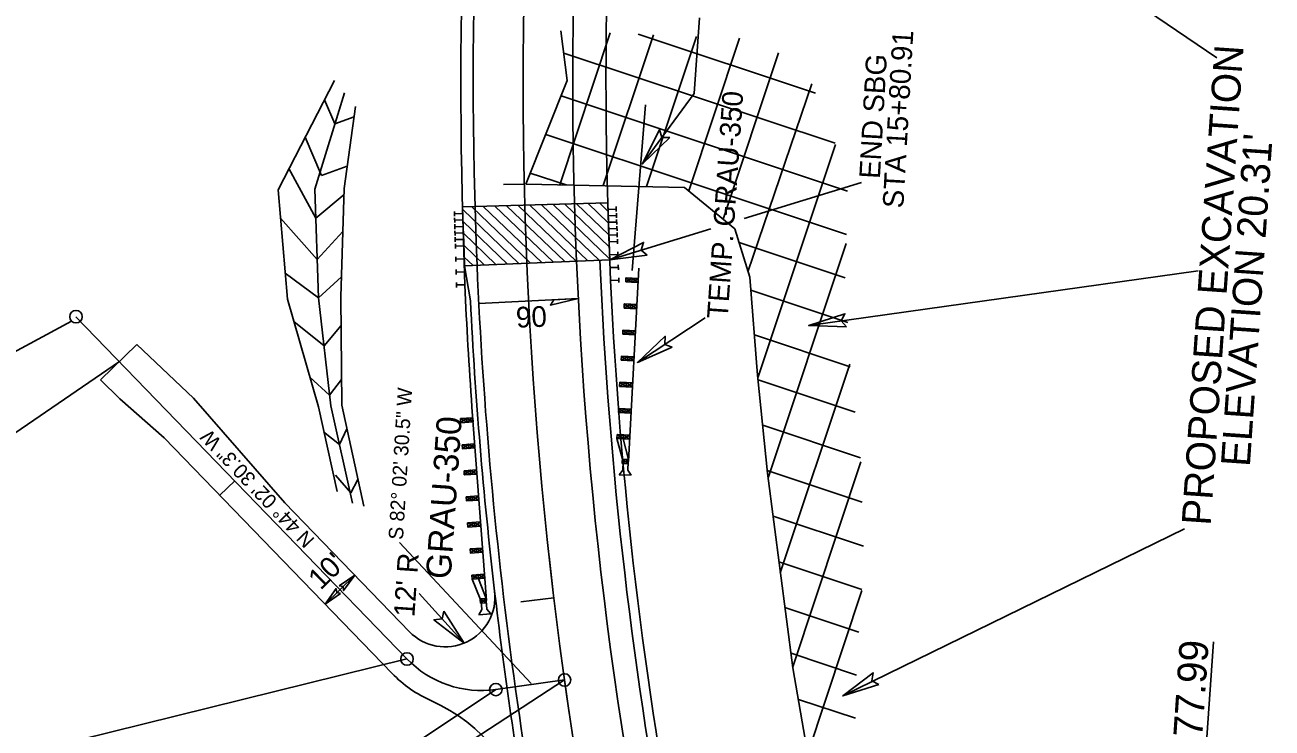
# Model space of a CAD drawing. Extents: x 2599146 to 2600072, y 728518 to 730269.
# Drawn here: x 2599320.7 to 2599621.3, y 729076.9 to 729246.4 of the extents above; entities that cross this region are included whole.
import ezdxf

# ---------------------------------------------------------------- set-up
doc = ezdxf.new("R2010")
doc.units = 0
for name, color, linetype in [('Default', 7, 'Continuous'), ('Old_Level_11', 7, 'Continuous'), ('Prop Conc Shoulder Berm Gutter', 7, 'Continuous'), ('Prop Dimension', 7, 'Continuous'), ('Prop Dimension Text', 7, 'Continuous'), ('Prop Drainage Ditch Base Lines', 7, 'Continuous'), ('Prop EOT', 7, 'Continuous'), ('Prop Guardrail', 7, 'Continuous'), ('Prop Guardrail Anchor Unit CELL', 7, 'Continuous'), ('Prop Horizontal Alignment', 7, 'Continuous'), ('Prop Horizontal Alignment Direction Label', 7, 'Continuous'), ('Prop Horizontal Alignment Station Label', 7, 'Continuous'), ('Prop Horizontal Alignment Tick Large', 7, 'Continuous'), ('Prop Horizontal Alignment Tick Small', 7, 'Continuous'), ('Prop Lane Lines', 7, 'Continuous'), ('Prop Roadway Bridge', 7, 'Continuous'), ('Prop Structure Anchor Unit CELL', 7, 'Continuous'), ('Prop Superelevation Label', 7, 'Continuous'), ('Prop Temporary Shoring', 7, 'Continuous'), ('Prop Temporary Shoring Leader Line', 7, 'Continuous'), ('Prop Temporary Shoring Text', 7, 'Continuous'), ('Prop Terminator CELL', 7, 'Continuous')]:
    doc.layers.add(name, color=color, linetype=linetype)

msp = doc.modelspace()

# ---------------------------------------------------------------- linework, layer by layer
at = {"layer": 'Default'}
for p, q in [((2599449.59, 729207.86), (2599461.77, 729244.49)), ((2599451.39, 729233.01), (2599449.88, 729244.99)), ((2599460.06, 729207.65), (2599472.16, 729244.05)), ((2599511.25, 729229.98), (2599468.49, 729244.2)), ((2599470.52, 729207.43), (2599482.56, 729243.61)), ((2599480.71, 729206.37), (2599492.95, 729243.17)), ((2599515.96, 729217.88), (2599450.55, 729239.63)), ((2599488.98, 729199.56), (2599502.34, 729239.71)), ((2599441.44, 729208.03), (2599451.39, 729233.01)), ((2599494.92, 729186.85), (2599510.38, 729232.21)), ((2599518.98, 729206.33), (2599449.91, 729229.31)), ((2599518.71, 729195.89), (2599446.21, 729220)), ((2599497.34, 729161.3), (2599516.06, 729217.61)), ((2599451.11, 729207.83), (2599442.5, 729210.69)), ((2599479.66, 729207.24), (2599441.44, 729208.03)), ((2599491.82, 729197.23), (2599479.66, 729207.24)), ((2599495.43, 729185.58), (2599491.82, 729197.23)), ((2599518.43, 729185.44), (2599492.83, 729193.95)), ((2599499.86, 729137.2), (2599518.65, 729193.69)), ((2599497.29, 729161.95), (2599495.43, 729185.58)), ((2599519.07, 729174.69), (2599495.68, 729182.47)), ((2599519.58, 729163.98), (2599496.52, 729171.65)), ((2599502.77, 729114.29), (2599519.51, 729164.6)), ((2599499.71, 729138.37), (2599497.29, 729161.95)), ((2599520.84, 729153.02), (2599497.4, 729160.82)), ((2599522.1, 729142.07), (2599498.52, 729149.91)), ((2599522.54, 729131.38), (2599499.63, 729139)), ((2599502.7, 729114.87), (2599499.71, 729138.37)), ((2599505.79, 729091.67), (2599522.21, 729141.04)), ((2599522.85, 729120.74), (2599501.03, 729128)), ((2599522.46, 729110.33), (2599502.43, 729116.99)), ((2599505.83, 729091.4), (2599502.7, 729114.87)), ((2599509.38, 729070.78), (2599522.44, 729110.03)), ((2599521.73, 729100.03), (2599503.88, 729105.97)), ((2599521.16, 729089.68), (2599505.36, 729094.94)), ((2599509.85, 729068.07), (2599505.83, 729091.4)), ((2599520.87, 729079.24), (2599507.14, 729083.81))]:
    msp.add_line(p, q, dxfattribs=at)
at = {"layer": 'Old_Level_11'}
msp.add_line((2599484.66, 729175.76), (2599468.34, 729165.03), dxfattribs=at)
at = {"layer": 'Prop Conc Shoulder Berm Gutter'}
msp.add_arc((2600480.74, 729232.47), 1022.34, 182.39886, 190.87052, dxfattribs=at)
at = {"layer": 'Prop Dimension'}
for p, q in [((2599509.48, 729305.39), (2599608.02, 729238.47)), ((2599494.07, 729199.72), (2599522.35, 729208.38)), ((2599461.64, 729189.78), (2599485.99, 729197.24)), ((2599509.63, 729173.91), (2599603.55, 729187.15)), ((2599517.84, 729084.66), (2599600.18, 729124.92)), ((2599400.18, 729113.75), (2599393, 729106.79))]:
    msp.add_line(p, q, dxfattribs=at)
at = {"layer": 'Prop Dimension Text'}
msp.add_line((2599415.68, 729109.34), (2599426.53, 729097.36), dxfattribs=at)
at = {"layer": 'Prop Drainage Ditch Base Lines'}
for p, q in [((2599381.67, 729206.63), (2599395.27, 729233.01)), ((2599390.55, 729206.83), (2599397.7, 729230.03)), ((2599395.38, 729222.52), (2599392.87, 729228.37)), ((2599397.63, 729207), (2599400.38, 729226.74)), ((2599395.38, 729222.52), (2599400.04, 729224.25)), ((2599392.18, 729210.07), (2599388.21, 729219.31)), ((2599390.79, 729199.83), (2599384.31, 729211.76)), ((2599392.18, 729210.07), (2599398.38, 729212.38)), ((2599383.95, 729180.28), (2599381.67, 729206.63)), ((2599391.46, 729180.64), (2599390.55, 729206.83)), ((2599390.79, 729199.83), (2599397.59, 729205.5)), ((2599396.85, 729180.89), (2599397.63, 729207)), ((2599391.14, 729189.82), (2599382.26, 729199.8)), ((2599391.14, 729189.82), (2599397.32, 729196.63)), ((2599391.46, 729180.64), (2599383.4, 729186.56)), ((2599391.46, 729180.64), (2599396.99, 729185.68)), ((2599394.39, 729154.57), (2599391.46, 729180.64)), ((2599397.05, 729154.76), (2599396.85, 729180.89)), ((2599391.43, 729154.36), (2599383.95, 729180.28)), ((2599392.76, 729169.06), (2599385.5, 729174.88)), ((2599392.76, 729169.06), (2599396.9, 729173.95)), ((2599394.1, 729157.16), (2599389.38, 729161.47)), ((2599394.1, 729157.16), (2599397, 729160.95)), ((2599395.91, 729133.9), (2599391.43, 729154.36)), ((2599399.62, 729131.1), (2599394.39, 729154.57)), ((2599402.34, 729130.42), (2599397.05, 729154.76)), ((2599396.46, 729145.29), (2599392.61, 729148.28)), ((2599396.46, 729145.29), (2599398.3, 729148.99)), ((2599399.26, 729133.57), (2599395.51, 729137.89)), ((2599399.26, 729133.57), (2599400.94, 729136.85))]:
    msp.add_line(p, q, dxfattribs=at)
at = {"layer": 'Prop EOT'}
for p, q in [((2599428.06, 729179.91), (2599426.67, 729188.31)), ((2599347.67, 729169.36), (2599338.88, 729160.85)), ((2599361.32, 729156.43), (2599347.67, 729169.36)), ((2599343.52, 729156.26), (2599338.88, 729160.85)), ((2599383.31, 729131.2), (2599361.32, 729156.43)), ((2599354.24, 729146.87), (2599343.52, 729156.26)), ((2599409.17, 729090.07), (2599354.24, 729146.87)), ((2599413.36, 729100.13), (2599383.31, 729131.2))]:
    msp.add_line(p, q, dxfattribs=at)
for centre, radius, start, end in [((2600480.74, 729232.47), 1052, 182.39886, 193.57808), ((2600480.74, 729232.47), 1028, 182.39886, 193.57808), ((2600480.74, 729232.47), 1054, 182.85838, 186.68017), ((2599421.98, 729108.47), 12, 224.0417, 6.6802), ((2600480.74, 729232.47), 1054, 186.68017, 189.77021), ((2599430.73, 729110.93), 30, 224.0417, 246.3139), ((2599402.61, 729046.82), 40, 9.7702, 66.3139)]:
    msp.add_arc(centre, radius, start, end, dxfattribs=at)
at = {"layer": 'Prop Guardrail'}
for centre, radius, start, end in [((2600477.16, 729229.69), 1051.44, 182.5033, 184.11474), ((2600478.29, 729232.3), 1017.56, 182.67771, 190.88783)]:
    msp.add_arc(centre, radius, start, end, dxfattribs=at)
at = {"layer": 'Prop Guardrail Anchor Unit CELL'}
for p, q in [((2599468.68, 729187.8), (2599466.16, 729141.12)), ((2599465.55, 729185.43), (2599465.49, 729184.43)), ((2599465.49, 729184.43), (2599467.04, 729185.35)), ((2599468.49, 729184.27), (2599465.49, 729184.43)), ((2599468.54, 729185.27), (2599465.55, 729185.43)), ((2599466.99, 729184.35), (2599465.55, 729185.43)), ((2599467.04, 729185.35), (2599466.99, 729184.35)), ((2599466.99, 729184.35), (2599468.54, 729185.27)), ((2599468.49, 729184.27), (2599466.99, 729184.35)), ((2599467.04, 729185.35), (2599468.49, 729184.27)), ((2599468.54, 729185.27), (2599468.49, 729184.27)), ((2599465.16, 729179.14), (2599465.1, 729178.14)), ((2599465.1, 729178.14), (2599466.68, 729179.06)), ((2599468.15, 729177.98), (2599465.1, 729178.14)), ((2599468.2, 729178.97), (2599465.16, 729179.14)), ((2599466.63, 729178.06), (2599465.16, 729179.14)), ((2599466.68, 729179.06), (2599466.63, 729178.06)), ((2599468.2, 729178.97), (2599466.63, 729178.06)), ((2599466.68, 729179.06), (2599468.15, 729177.98)), ((2599464.82, 729172.85), (2599464.77, 729171.85)), ((2599464.77, 729171.85), (2599466.34, 729172.76)), ((2599467.81, 729171.68), (2599464.77, 729171.85)), ((2599467.86, 729172.68), (2599464.82, 729172.85)), ((2599466.29, 729171.76), (2599464.82, 729172.85)), ((2599466.34, 729172.76), (2599466.29, 729171.76)), ((2599467.86, 729172.68), (2599466.29, 729171.76)), ((2599466.34, 729172.76), (2599467.81, 729171.68)), ((2599464.49, 729166.55), (2599464.44, 729165.55)), ((2599464.44, 729165.55), (2599466.01, 729166.47)), ((2599467.47, 729165.39), (2599464.44, 729165.55)), ((2599467.53, 729166.39), (2599464.49, 729166.55)), ((2599465.96, 729165.47), (2599464.49, 729166.55)), ((2599466.01, 729166.47), (2599465.96, 729165.47)), ((2599467.53, 729166.39), (2599465.96, 729165.47)), ((2599466.01, 729166.47), (2599467.47, 729165.39)), ((2599467.53, 729166.39), (2599467.47, 729165.39)), ((2599464.05, 729160.27), (2599464, 729159.27)), ((2599464, 729159.27), (2599465.62, 729160.18)), ((2599467.19, 729160.1), (2599464.05, 729160.27)), ((2599465.57, 729159.18), (2599464.05, 729160.27)), ((2599465.62, 729160.18), (2599465.57, 729159.18)), ((2599467.19, 729160.1), (2599465.57, 729159.18)), ((2599465.62, 729160.18), (2599467.13, 729159.1)), ((2599467.13, 729159.1), (2599464, 729159.27)), ((2599428.43, 729154.24), (2599431.91, 729107.62)), ((2599463.85, 729153.97), (2599463.8, 729152.97)), ((2599463.8, 729152.97), (2599465.35, 729153.89)), ((2599466.85, 729153.81), (2599463.85, 729153.97)), ((2599465.29, 729152.89), (2599463.85, 729153.97)), ((2599465.35, 729153.89), (2599465.29, 729152.89)), ((2599466.85, 729153.81), (2599465.29, 729152.89)), ((2599465.35, 729153.89), (2599466.79, 729152.81)), ((2599428.62, 729151.71), (2599425.63, 729151.49)), ((2599427.2, 729150.6), (2599425.63, 729151.49)), ((2599425.63, 729151.49), (2599425.7, 729150.49)), ((2599425.7, 729150.49), (2599427.13, 729151.6)), ((2599428.7, 729150.71), (2599425.7, 729150.49)), ((2599427.13, 729151.6), (2599427.2, 729150.6)), ((2599427.13, 729151.6), (2599428.7, 729150.71)), ((2599427.2, 729150.6), (2599428.62, 729151.71)), ((2599428.7, 729150.71), (2599427.2, 729150.6)), ((2599428.62, 729151.71), (2599428.7, 729150.71)), ((2599466.79, 729152.81), (2599463.8, 729152.97)), ((2599463.45, 729147.68), (2599463.39, 729146.68)), ((2599463.39, 729146.68), (2599464.98, 729147.6)), ((2599466.51, 729147.51), (2599463.45, 729147.68)), ((2599464.92, 729146.6), (2599463.45, 729147.68)), ((2599464.98, 729147.6), (2599464.92, 729146.6)), ((2599466.51, 729147.51), (2599464.92, 729146.6)), ((2599464.98, 729147.6), (2599466.45, 729146.51)), ((2599429.09, 729145.43), (2599426.05, 729145.2)), ((2599427.64, 729144.31), (2599426.05, 729145.2)), ((2599426.05, 729145.2), (2599426.12, 729144.2)), ((2599426.12, 729144.2), (2599427.57, 729145.31)), ((2599429.17, 729144.43), (2599426.12, 729144.2)), ((2599427.57, 729145.31), (2599427.64, 729144.31)), ((2599427.57, 729145.31), (2599429.17, 729144.43)), ((2599429.09, 729145.43), (2599427.64, 729144.31)), ((2599466.45, 729146.51), (2599463.39, 729146.68)), ((2599463.39, 729146.68), (2599464.69, 729141.7)), ((2599464.92, 729146.6), (2599466.19, 729141.62)), ((2599464.69, 729141.7), (2599464.64, 729140.7)), ((2599464.64, 729140.7), (2599466.19, 729141.62)), ((2599464.69, 729141.7), (2599464.66, 729141.2)), ((2599466.19, 729141.62), (2599464.69, 729141.7)), ((2599466.14, 729140.62), (2599464.69, 729141.7)), ((2599429.56, 729139.14), (2599426.52, 729138.92)), ((2599428.11, 729138.03), (2599426.52, 729138.92)), ((2599426.52, 729138.92), (2599426.59, 729137.92)), ((2599426.59, 729137.92), (2599428.04, 729139.03)), ((2599428.04, 729139.03), (2599428.11, 729138.03)), ((2599428.04, 729139.03), (2599429.63, 729138.14)), ((2599429.56, 729139.14), (2599428.11, 729138.03)), ((2599463.89, 729137.95), (2599464.79, 729139.09)), ((2599466.14, 729140.62), (2599464.64, 729140.7)), ((2599464.79, 729139.09), (2599464.86, 729141.14)), ((2599464.86, 729141.14), (2599465.47, 729141.12)), ((2599465.47, 729141.12), (2599466.09, 729141.09)), ((2599466.09, 729141.09), (2599466.01, 729139.05)), ((2599466.01, 729139.05), (2599466.83, 729137.84)), ((2599429.63, 729138.14), (2599426.59, 729137.92)), ((2599466.83, 729137.84), (2599463.89, 729137.95)), ((2599430.03, 729132.86), (2599427, 729132.63)), ((2599428.59, 729131.75), (2599427, 729132.63)), ((2599427, 729132.63), (2599427.08, 729131.64)), ((2599427.08, 729131.64), (2599428.51, 729132.74)), ((2599428.51, 729132.74), (2599428.59, 729131.75)), ((2599428.51, 729132.74), (2599430.1, 729131.86)), ((2599430.03, 729132.86), (2599428.59, 729131.75)), ((2599430.03, 729132.86), (2599430.1, 729131.86)), ((2599430.1, 729131.86), (2599427.08, 729131.64)), ((2599430.5, 729126.57), (2599427.37, 729126.34)), ((2599429.01, 729125.46), (2599427.37, 729126.34)), ((2599427.37, 729126.34), (2599427.44, 729125.34)), ((2599427.44, 729125.34), (2599428.93, 729126.46)), ((2599428.93, 729126.46), (2599429.01, 729125.46)), ((2599428.93, 729126.46), (2599430.57, 729125.58)), ((2599430.5, 729126.57), (2599429.01, 729125.46)), ((2599430.57, 729125.58), (2599427.44, 729125.34)), ((2599430.97, 729120.29), (2599427.98, 729120.07)), ((2599429.54, 729119.18), (2599427.98, 729120.07)), ((2599427.98, 729120.07), (2599428.05, 729119.07)), ((2599428.05, 729119.07), (2599429.47, 729120.18)), ((2599431.04, 729119.29), (2599428.05, 729119.07)), ((2599429.47, 729120.18), (2599429.54, 729119.18)), ((2599429.47, 729120.18), (2599431.04, 729119.29)), ((2599430.97, 729120.29), (2599429.54, 729119.18)), ((2599431.44, 729114.01), (2599428.38, 729113.78)), ((2599429.98, 729112.89), (2599428.38, 729113.78)), ((2599428.38, 729113.78), (2599428.45, 729112.78)), ((2599428.45, 729112.78), (2599429.91, 729113.89)), ((2599431.51, 729113.01), (2599428.45, 729112.78)), ((2599428.45, 729112.78), (2599430.38, 729108.01)), ((2599429.91, 729113.89), (2599429.98, 729112.89)), ((2599429.91, 729113.89), (2599431.51, 729113.01)), ((2599431.44, 729114.01), (2599429.98, 729112.89)), ((2599429.98, 729112.89), (2599431.87, 729108.12)), ((2599430.07, 729104.18), (2599430.81, 729105.44)), ((2599431.87, 729108.12), (2599430.38, 729108.01)), ((2599430.38, 729108.01), (2599430.42, 729107.51)), ((2599431.95, 729107.12), (2599430.38, 729108.01)), ((2599430.38, 729108.01), (2599430.45, 729107.01)), ((2599430.45, 729107.01), (2599431.87, 729108.12)), ((2599431.95, 729107.12), (2599430.45, 729107.01)), ((2599430.62, 729107.47), (2599431.23, 729107.53)), ((2599430.81, 729105.44), (2599430.62, 729107.47)), ((2599431.23, 729107.53), (2599431.84, 729107.59)), ((2599431.84, 729107.59), (2599432.03, 729105.55)), ((2599432.03, 729105.55), (2599432.99, 729104.46)), ((2599432.99, 729104.46), (2599430.07, 729104.18))]:
    msp.add_line(p, q, dxfattribs=at)
at = {"layer": 'Prop Horizontal Alignment'}
for p, q in [((2599412.76, 729093.55), (2599332.96, 729176.06)), ((2599450.76, 729088.48), (2599434.19, 729086.17))]:
    msp.add_line(p, q, dxfattribs=at)
for centre, radius, start, end in [((2600480.74, 729232.47), 1040, 170.73628, 193.57808), ((2599430.73, 729110.93), 25, 224.0417, 277.9582)]:
    msp.add_arc(centre, radius, start, end, dxfattribs=at)
at = {"layer": 'Prop Horizontal Alignment Station Label'}
for p, q in [((2599331.88, 729175.02), (2599230.16, 729120.09)), ((2599261.14, 729108.91), (2599343.42, 729165.25)), ((2599442.74, 729087.6), (2599410.96, 729121.63)), ((2599601.83, 729020.2), (2599607.18, 729097.66)), ((2599290.96, 729063.51), (2599412.76, 729093.55)), ((2599450.76, 729088.48), (2599370.11, 729036)), ((2599339.07, 729022.96), (2599434.19, 729086.17))]:
    msp.add_line(p, q, dxfattribs=at)
for centre in [(2599332.96, 729176.06), (2599412.76, 729093.55), (2599434.19, 729086.17), (2599450.76, 729088.48)]:
    msp.add_circle(centre, 1.5, dxfattribs=at)
at = {"layer": 'Prop Horizontal Alignment Tick Large'}
for p, q in [((2599447.04, 729118.25), (2599447.91, 729110.3)), ((2599448.18, 729108.32), (2599440.24, 729107.36)), ((2599450.76, 729088.48), (2599451.87, 729080.56))]:
    msp.add_line(p, q, dxfattribs=at)
at = {"layer": 'Prop Horizontal Alignment Tick Small'}
for p, q in [((2599441.03, 729208.02), (2599436.03, 729207.9)), ((2599371.23, 729136.5), (2599367.63, 729133.02))]:
    msp.add_line(p, q, dxfattribs=at)
at = {"layer": 'Prop Lane Lines'}
for radius, start in [(1028, 172.27238), (1052, 172.59246)]:
    msp.add_arc((2600480.74, 729232.47), radius, start, 182.39886, dxfattribs=at)
at = {"layer": 'Prop Roadway Bridge'}
for p, q in [((2599426.17, 729202.51), (2599461.16, 729203.5)), ((2599439.75, 729188.86), (2599426.19, 729201.89)), ((2599442.52, 729188.98), (2599428.37, 729202.57)), ((2599445.29, 729189.09), (2599431.17, 729202.65)), ((2599448.05, 729189.21), (2599433.98, 729202.73)), ((2599450.82, 729189.33), (2599436.78, 729202.81)), ((2599453.59, 729189.44), (2599439.59, 729202.89)), ((2599456.35, 729189.56), (2599442.39, 729202.97)), ((2599459.12, 729189.67), (2599445.19, 729203.05)), ((2599461.63, 729190.04), (2599448, 729203.13)), ((2599461.51, 729192.92), (2599450.8, 729203.21)), ((2599461.4, 729195.8), (2599453.61, 729203.29)), ((2599461.3, 729198.67), (2599456.41, 729203.37)), ((2599461.21, 729201.53), (2599459.22, 729203.45)), ((2599436.99, 729188.75), (2599426.27, 729199.03)), ((2599434.22, 729188.63), (2599426.37, 729196.17)), ((2599431.45, 729188.51), (2599426.47, 729193.3)), ((2599428.69, 729188.4), (2599426.58, 729190.42)), ((2599461.64, 729189.78), (2599426.67, 729188.31))]:
    msp.add_line(p, q, dxfattribs=at)
for radius in [1055, 1020]:
    msp.add_arc((2600480.74, 729232.47), radius, 172.59247, 182.39886, dxfattribs=at)
at = {"layer": 'Prop Structure Anchor Unit CELL'}
for p, q in [((2599426.17, 729202.51), (2599426.73, 729183.77)), ((2599461.16, 729203.5), (2599461.84, 729184.76)), ((2599461.21, 729201.94), (2599463.21, 729202.01)), ((2599463.19, 729202.59), (2599463.23, 729201.44)), ((2599424.2, 729201.46), (2599424.23, 729200.31)), ((2599426.22, 729200.95), (2599424.22, 729200.89)), ((2599424.25, 729199.9), (2599424.28, 729198.75)), ((2599426.26, 729199.38), (2599424.26, 729199.32)), ((2599461.27, 729200.38), (2599463.27, 729200.45)), ((2599461.33, 729198.82), (2599463.33, 729198.89)), ((2599463.25, 729201.02), (2599463.29, 729199.88)), ((2599463.31, 729199.46), (2599463.35, 729198.32)), ((2599424.29, 729198.34), (2599424.33, 729197.19)), ((2599426.31, 729197.82), (2599424.31, 729197.76)), ((2599424.34, 729196.77), (2599424.37, 729195.63)), ((2599426.36, 729196.26), (2599424.36, 729196.2)), ((2599461.39, 729197.26), (2599463.38, 729197.33)), ((2599461.44, 729195.69), (2599463.44, 729195.77)), ((2599463.36, 729197.9), (2599463.4, 729196.76)), ((2599463.42, 729196.34), (2599463.46, 729195.2)), ((2599424.39, 729195.21), (2599424.42, 729194.07)), ((2599426.4, 729194.7), (2599424.4, 729194.64)), ((2599424.43, 729193.65), (2599424.47, 729192.5)), ((2599426.45, 729193.14), (2599424.45, 729193.08)), ((2599461.5, 729194.13), (2599463.5, 729194.21)), ((2599463.48, 729194.78), (2599463.52, 729193.63)), ((2599424.52, 729190.53), (2599424.56, 729189.38)), ((2599426.54, 729190.01), (2599424.54, 729189.95)), ((2599461.61, 729191.01), (2599463.61, 729191.08)), ((2599463.59, 729191.66), (2599463.63, 729190.51)), ((2599424.62, 729187.4), (2599424.65, 729186.26)), ((2599426.63, 729186.89), (2599424.63, 729186.83)), ((2599461.73, 729187.89), (2599463.73, 729187.96)), ((2599463.71, 729188.53), (2599463.75, 729187.39)), ((2599424.71, 729184.28), (2599424.74, 729183.13)), ((2599426.73, 729183.77), (2599424.73, 729183.71)), ((2599461.84, 729184.76), (2599463.84, 729184.84)), ((2599463.82, 729185.41), (2599463.86, 729184.27))]:
    msp.add_line(p, q, dxfattribs=at)
at = {"layer": 'Prop Superelevation Label'}
msp.add_line((2599430.09, 729179.21), (2599454.06, 729180.43), dxfattribs=at)
at = {"layer": 'Prop Temporary Shoring'}
msp.add_line((2599470.26, 729227.17), (2599467.06, 729187.16), dxfattribs=at)
at = {"layer": 'Prop Temporary Shoring Leader Line'}
msp.add_line((2599469.58, 729212.91), (2599481.99, 729229.88), dxfattribs=at)
at = {"layer": 'Prop Temporary Shoring Text'}
msp.add_line((2599481.99, 729229.88), (2599483.25, 729248.1), dxfattribs=at)
msp.add_lwpolyline([(2599476.14, 729219.26), (2599469.58, 729212.91), (2599473.63, 729221.16), (2599474.24, 729219.29)], close=True, dxfattribs=at)
at = {"layer": 'Prop Terminator CELL'}
for points in [[(2599470.7, 729190.93), (2599461.64, 729189.78), (2599469.82, 729193.96), (2599469.19, 729192.09)], [(2599454.06, 729180.43), (2599447.34, 729178.88), (2599448.15, 729180.13)], [(2599518.76, 729173.65), (2599509.63, 729173.91), (2599518.36, 729176.78), (2599517.45, 729175.03)], [(2599476.71, 729168.68), (2599468.34, 729165.03), (2599475.02, 729171.34), (2599474.94, 729169.37)], [(2599396.41, 729111.17), (2599400.18, 729113.75), (2599397.49, 729110.02), (2599397.35, 729111)], [(2599396.77, 729109.36), (2599393, 729106.79), (2599395.69, 729110.51), (2599395.84, 729109.54)], [(2599421.64, 729105.07), (2599426.53, 729097.36), (2599419.27, 729102.99), (2599421.23, 729103.22)], [(2599526.55, 729087.41), (2599517.84, 729084.66), (2599525.15, 729090.23), (2599524.86, 729088.28)]]:
    msp.add_lwpolyline(points, close=True, dxfattribs=at)

# ---------------------------------------------------------------- texts
at = {"layer": 'Default'}
for s, p in [('PROPOSED EXCAVATION', (2599606.51, 729125.6)), ("ELEVATION 20.31'", (2599615.96, 729139.76))]:
    msp.add_text(s, height=7, rotation=86.0601, dxfattribs=at).set_placement(p)
at = {"layer": 'Old_Level_11'}
msp.add_text('TEMP. GRAU-350', height=5, rotation=86.05, dxfattribs=at).set_placement((2599490.07, 729175.42))
at = {"layer": 'Prop Dimension Text'}
for s, rotation, p in [('STA 15+80.91', 86.7377, (2599532.42, 729202.11)), ('END SBG', 86.7377, (2599526.78, 729209.22)), ("10'", 44.4387, (2599391.95, 729109.98)), ("12' R", 86.05, (2599414.54, 729103.57))]:
    msp.add_text(s, height=5, rotation=rotation, dxfattribs=at).set_placement(p)
at = {"layer": 'Prop Horizontal Alignment Direction Label'}
for s, rotation, p in [('S 82%%d 02\' 30.5" W', 86.5074, (2599411.8, 729122.21)), ('N 44%%d 02\' 30.3" W', 133.6115, (2599390.69, 729122.4))]:
    msp.add_text(s, height=3.5, rotation=rotation, dxfattribs=at).set_placement(p)
at = {"layer": 'Prop Horizontal Alignment Station Label'}
msp.add_text('PC Sta.  13+77.99', height=7, rotation=86.1217, dxfattribs=at).set_placement((2599600.88, 729021.28))
at = {"layer": 'Prop Structure Anchor Unit CELL'}
msp.add_text('GRAU-350', height=6, rotation=86.0601, dxfattribs=at).set_placement((2599423.29, 729112.68))
at = {"layer": 'Prop Superelevation Label'}
msp.add_text('06', height=5, rotation=182.0765, dxfattribs=at).set_placement((2599446.38, 729178.67))

doc.saveas('drawing.dxf')
